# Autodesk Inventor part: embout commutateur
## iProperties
Author: Administrateur
Created: 2001-04
Part Number: embout commutateur
Material: Par défaut
Document SubType Name: Modélisation
Designer: Administrateur
Control State: 0
Master: False
Checked Out: False
PropertySet Name: Design Tracking Control
Shininess: 0.0
PropertySet Name: _Private Model Information
Length Units: 11269
Angle Units: 11283
Time Units: 11279
Mass Units: 11290
Length Display Precision: 3
Angle Display Precision: 2
Compacted: False
Density: 0.0
Volumn: 0.0
Area: 0.0
PropertySet Name: Model Information
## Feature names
1. Perçage1 [Hole]
